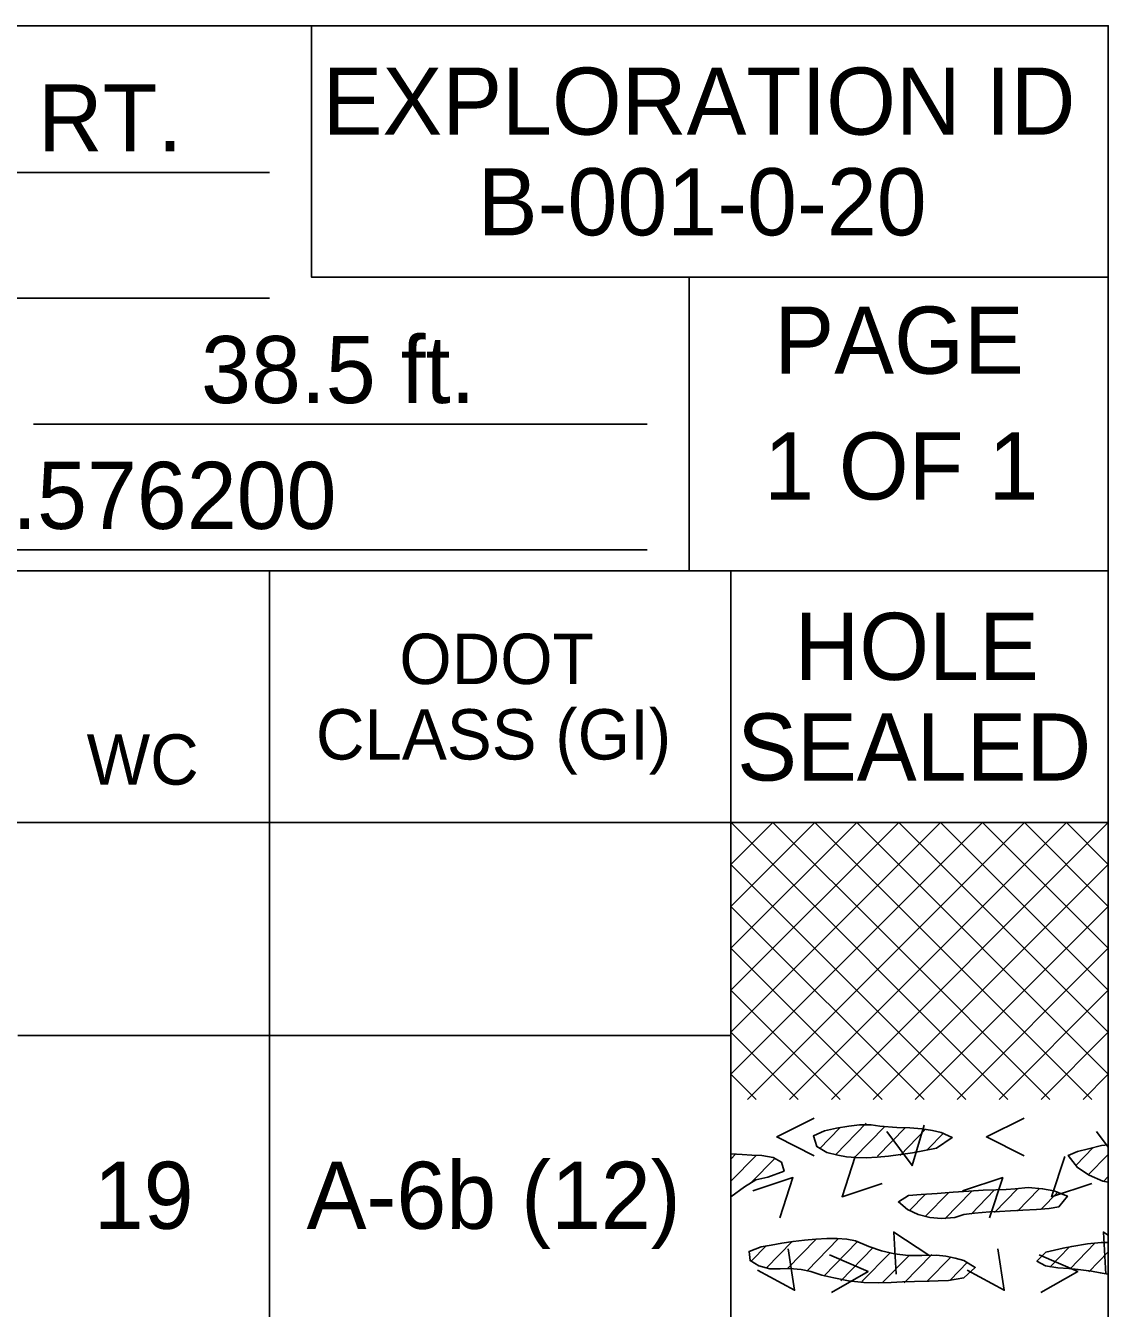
# Model space of a CAD drawing. Extents: x 0 to 0.833, y -0.323 to 0.608.
# Drawn here: x 0.7258 to 0.8333, y 0.4809 to 0.6083 of the extents above; entities that cross this region are included whole.
import ezdxf

# ---------------------------------------------------------------- set-up
doc = ezdxf.new("R2010")
doc.units = 0

msp = doc.modelspace()

# ---------------------------------------------------------------- linework, layer by layer
for points in [[(0, -0.32328), (0.83333, -0.32328), (0.83333, 0.60833), (0, 0.60833)], [(0.81233, 0.49887), (0.81063, 0.49899), (0.80977, 0.49912), (0.8086, 0.49913), (0.80755, 0.49899), (0.80632, 0.49879), (0.80513, 0.49854), (0.80403, 0.49802), (0.80436, 0.49696), (0.80536, 0.49639), (0.80647, 0.4961), (0.8073, 0.49595), (0.80824, 0.49587), (0.80926, 0.49586), (0.81035, 0.49591), (0.81149, 0.49601), (0.81267, 0.49616), (0.81386, 0.49635), (0.81506, 0.49656), (0.81625, 0.49679), (0.81783, 0.49787), (0.81673, 0.49837), (0.81585, 0.49857), (0.8148, 0.49873), (0.81361, 0.49883)], [(0.83265, 0.49706), (0.83136, 0.49675), (0.83028, 0.49647), (0.82934, 0.49608), (0.83026, 0.49488), (0.83142, 0.49412), (0.83279, 0.49354), (0.83333, 0.49344), (0.83333, 0.49715)], [(0.79583, 0.49196), (0.79719, 0.49295), (0.79831, 0.49365), (0.79951, 0.49392), (0.80111, 0.49453), (0.80086, 0.49541), (0.80002, 0.49589), (0.79889, 0.49608), (0.79791, 0.49611), (0.79694, 0.49617), (0.79583, 0.49625)], [(0.82537, 0.4929), (0.82408, 0.49276), (0.82319, 0.4927), (0.82214, 0.49267), (0.82091, 0.49264), (0.81947, 0.49254), (0.81792, 0.49242), (0.81632, 0.4923), (0.81475, 0.49221), (0.81348, 0.49211), (0.81247, 0.49147), (0.81337, 0.49071), (0.81444, 0.49021), (0.81561, 0.48992), (0.81675, 0.48981), (0.81807, 0.48993), (0.81896, 0.4902), (0.82003, 0.49035), (0.82157, 0.49047), (0.82253, 0.49052), (0.82362, 0.49058), (0.82483, 0.49064), (0.82618, 0.49071), (0.82745, 0.49082), (0.82842, 0.49099), (0.82927, 0.49205), (0.82791, 0.49257), (0.82679, 0.49277)], [(0.79885, 0.487), (0.79763, 0.48654), (0.79773, 0.48564), (0.79859, 0.48512), (0.7997, 0.48482), (0.80074, 0.48483), (0.80165, 0.48484), (0.80281, 0.48476), (0.80377, 0.48455), (0.80486, 0.4842), (0.80606, 0.48391), (0.80751, 0.48363), (0.80905, 0.48345), (0.81052, 0.48342), (0.81177, 0.48347), (0.81289, 0.48351), (0.81408, 0.48355), (0.81553, 0.48359), (0.81642, 0.48362), (0.81745, 0.48365), (0.81897, 0.48392), (0.82011, 0.48496), (0.81896, 0.48563), (0.8181, 0.48589), (0.81717, 0.48609), (0.81626, 0.48619), (0.81479, 0.48614), (0.81343, 0.48614), (0.8121, 0.48629), (0.8108, 0.48659), (0.80953, 0.48705), (0.8082, 0.4876), (0.80736, 0.48776), (0.8064, 0.48784), (0.80536, 0.48784), (0.80427, 0.48778), (0.80314, 0.48767), (0.80201, 0.48752), (0.8009, 0.48735), (0.79984, 0.48717)], [(0.83263, 0.48744), (0.83126, 0.4873), (0.82969, 0.48704), (0.82883, 0.48687), (0.82712, 0.48646), (0.82623, 0.48559), (0.82708, 0.4851), (0.82831, 0.48491), (0.82941, 0.48484), (0.83033, 0.48475), (0.83165, 0.48457), (0.83253, 0.48443), (0.83333, 0.48429), (0.83333, 0.48744)]]:
    msp.add_lwpolyline(points, close=True)
for points in [[(0.75417, 0.60833), (0.75417, 0.58333), (0.83333, 0.58333)], [(0.67111, 0.59375), (0.75, 0.59375)], [(0.79167, 0.55417), (0.79167, 0.58333)], [(0.64014, 0.58125), (0.75, 0.58125)], [(0.72653, 0.56875), (0.7875, 0.56875)], [(0.63722, 0.55625), (0.7875, 0.55625)], [(0, 0.55417), (0.83333, 0.55417)], [(0, 0.55417), (0.83333, 0.55417)], [(0, 0.55417), (0.83333, 0.55417)], [(0, 0.55417), (0.83333, 0.55417)], [(0, 0.55417), (0.83333, 0.55417)], [(0.75, 0.55417), (0.75, -0.28575)], [(0.75, 0.55417), (0.75, -0.28575)], [(0.79583, 0.55417), (0.79583, -0.28575)], [(0, 0.52917), (0.83333, 0.52917)], [(0, 0.52917), (0.83333, 0.52917)], [(0, 0.52917), (0.83333, 0.52917)], [(0, 0.52917), (0.83333, 0.52917)], [(0, 0.52917), (0.83333, 0.52917)], [(0.79583, 0.525), (0.8, 0.52917)], [(0.79583, 0.52083), (0.80417, 0.52917)], [(0.79583, 0.51667), (0.80833, 0.52917)], [(0.79583, 0.5125), (0.8125, 0.52917)], [(0.79583, 0.50833), (0.81667, 0.52917)], [(0.79583, 0.50417), (0.82083, 0.52917)], [(0.79585, 0.52917), (0.79589, 0.52912), (0.82336, 0.50165)], [(0.79748, 0.50165), (0.825, 0.52917)], [(0.80001, 0.52917), (0.81151, 0.51766), (0.82752, 0.50165)], [(0.80165, 0.50165), (0.82917, 0.52917)], [(0.80417, 0.52917), (0.82717, 0.50617), (0.83169, 0.50165)], [(0.80582, 0.50165), (0.83333, 0.52917)], [(0.80833, 0.52917), (0.83333, 0.50417)], [(0.8125, 0.52917), (0.83333, 0.50833)], [(0.81667, 0.52917), (0.83333, 0.5125)], [(0.82083, 0.52917), (0.83333, 0.51667)], [(0.825, 0.52917), (0.83333, 0.52083)], [(0.82917, 0.52917), (0.83333, 0.525)], [(0.83333, 0.52917), (0.83333, 0.52917)], [(0.83333, 0.50165), (0.83333, 0.52917)], [(0.79583, 0.525), (0.81918, 0.50165)], [(0.80998, 0.50165), (0.83333, 0.525)], [(0.79583, 0.52083), (0.81502, 0.50165)], [(0.81415, 0.50165), (0.83333, 0.52083)], [(0.79583, 0.51667), (0.81085, 0.50165)], [(0.81832, 0.50165), (0.83333, 0.51667)], [(0.79583, 0.5125), (0.80668, 0.50165)], [(0.82248, 0.50165), (0.83333, 0.5125)], [(0.725, 0.508), (0.75, 0.508)], [(0.75, 0.508), (0.79583, 0.508)], [(0.79583, 0.50833), (0.80252, 0.50165)], [(0.82665, 0.50165), (0.83333, 0.50833)], [(0.79583, 0.50417), (0.79835, 0.50165)], [(0.83082, 0.50165), (0.83333, 0.50417)], [(0.83333, -0.28575), (0.83333, 0.50165)], [(0.80412, 0.4998), (0.80038, 0.49792), (0.80412, 0.49605)], [(0.82496, 0.4998), (0.82121, 0.49792), (0.82496, 0.49605)], [(0.80465, 0.49675), (0.80667, 0.49883)], [(0.80626, 0.49619), (0.80928, 0.49928)], [(0.80809, 0.49585), (0.81111, 0.49895)], [(0.81041, 0.49602), (0.81318, 0.49885)], [(0.81134, 0.49846), (0.81384, 0.49508), (0.81503, 0.49908)], [(0.81264, 0.49609), (0.81518, 0.49869)], [(0.81536, 0.49667), (0.81699, 0.49833)], [(0.83217, 0.49846), (0.83333, 0.49689)], [(0.7963, 0.49621), (0.79583, 0.49572)], [(0.79834, 0.49608), (0.79583, 0.49351)], [(0.79786, 0.49338), (0.80023, 0.49581)], [(0.80818, 0.49597), (0.80687, 0.49197), (0.81087, 0.49328)], [(0.82901, 0.49597), (0.8277, 0.49197), (0.8317, 0.49328)], [(0.8301, 0.49509), (0.83184, 0.49687)], [(0.83131, 0.49412), (0.83333, 0.49619)], [(0.80069, 0.48989), (0.802, 0.49389), (0.798, 0.49257)], [(0.82152, 0.48989), (0.82284, 0.49389), (0.81884, 0.49257)], [(0.83285, 0.49349), (0.83333, 0.49398)], [(0.81519, 0.49228), (0.81354, 0.49058)], [(0.81514, 0.49001), (0.81748, 0.49241)], [(0.81709, 0.4898), (0.81974, 0.49251)], [(0.8197, 0.49025), (0.82203, 0.49265)], [(0.82202, 0.49041), (0.8243, 0.49275)], [(0.82431, 0.49055), (0.82644, 0.49274)], [(0.82663, 0.49071), (0.82834, 0.49247)], [(0.81551, 0.48616), (0.81201, 0.48847), (0.81226, 0.48428)], [(0.83333, 0.48815), (0.83284, 0.48847), (0.83309, 0.48428)], [(0.79938, 0.48713), (0.79786, 0.48558)], [(0.79933, 0.48487), (0.80195, 0.48756)], [(0.80142, 0.4848), (0.8043, 0.48775)], [(0.80653, 0.48783), (0.8034, 0.48461)], [(0.80506, 0.4841), (0.8084, 0.48752)], [(0.80997, 0.48693), (0.80675, 0.48362)], [(0.82751, 0.48498), (0.82945, 0.48696)], [(0.83203, 0.48739), (0.82949, 0.48479)], [(0.79847, 0.48468), (0.80215, 0.48268), (0.80153, 0.4868)], [(0.80562, 0.48622), (0.80946, 0.48454), (0.80581, 0.48248)], [(0.81164, 0.48642), (0.80884, 0.48356)], [(0.81353, 0.48614), (0.81094, 0.48349)], [(0.81303, 0.48342), (0.81579, 0.48625)], [(0.81534, 0.48358), (0.81768, 0.48597)], [(0.8193, 0.48468), (0.82299, 0.48268), (0.82236, 0.4868)], [(0.82645, 0.48622), (0.83029, 0.48454), (0.82664, 0.48248)], [(0.83138, 0.48452), (0.83333, 0.48652)], [(0.8176, 0.48368), (0.81934, 0.48547)], [(0.83333, 0.4843), (0.83333, 0.4843)]]:
    msp.add_lwpolyline(points)

# ---------------------------------------------------------------- texts
for s, height, p in [('EXPLORATION ID', 0.0066667, (0.75526, 0.5975)), ("347+67, 18' RT.", 0.0066667, (0.67793, 0.59583)), ('B-001-0-20', 0.006667, (0.77068, 0.5875)), ('PAGE', 0.006667, (0.80015, 0.57375)), ('38.5 ft.', 0.006667, (0.74319, 0.57083)), ('1 OF 1', 0.006667, (0.79912, 0.56125)), ('39.367200, -84.576200', 0.0066667, (0.66444, 0.55833)), ('HOLE', 0.006667, (0.80215, 0.54333)), ('ODOT', 0.005, (0.76289, 0.54292)), ('CLASS (GI)', 0.005, (0.7546, 0.53542)), ('SEALED', 0.006667, (0.79645, 0.53333)), ('WC', 0.005, (0.73182, 0.53292)), ('A-6b (12)', 0.006667, (0.75368, 0.48879)), ('19', 0.006667, (0.73253, 0.48879))]:
    msp.add_text(s, height=height).set_placement(p)

doc.saveas('drawing.dxf')
